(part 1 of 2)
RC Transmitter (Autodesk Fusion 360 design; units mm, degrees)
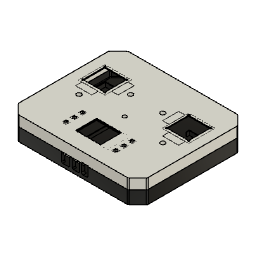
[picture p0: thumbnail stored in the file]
sketch "Skizze3" plane through (0, 0, 0) normal (0, 0, 1) x axis (1, 0, 0)
  line L1 (-100, 70) -> (-100, 0)
  line L2 (-85, 85) -> (-100, 70)
  line L3 (85, 85) -> (-85, 85)
  line L4 (100, 70) -> (85, 85)
  line L5 (100, -70) -> (100, 70)
  line L6 (85, -85) -> (100, -70)
  line L7 (-85, -85) -> (85, -85)
  line L8 (-100, -70) -> (-85, -85)
  line L9 (-100, 0) -> (-100, -70)
  line L10 (-95, 67.5) -> (-95, 0)
  line L11 (-82.5, 80) -> (0, 80)
  line L12 (-82.5, 80) -> (-95, 67.5)
  line L13 (82.5, 80) -> (0, 80)
  line L14 (95, 67.5) -> (95, 0)
  line L15 (82.5, 80) -> (95, 67.5)
  line L16 (95, -67.5) -> (95, 0)
  line L17 (-95, -67.5) -> (-95, 0)
  line L18 (-82.5, -80) -> (0, -80)
  line L19 (82.5, -80) -> (0, -80)
  line L20 (95, -67.5) -> (82.5, -80)
  line L21 (-95, -67.5) -> (-82.5, -80)
  point P11 (-95, 0)
  point P12 (-95, 67.5)
  point P13 (0, 80)
  point P14 (-82.5, 80)
  point P15 (82.5, 80)
  point P16 (95, 0)
  point P17 (95, 67.5)
  point P18 (95, -67.5)
  point P19 (-95, -67.5)
  point P20 (0, -80)
  point P21 (-82.5, -80)
  point P22 (82.5, -80)
  vertical L1
  perpendicular L1 L3
  perpendicular L3 L5
  perpendicular L4 L6
  perpendicular L5 L7
  perpendicular L6 L8
  perpendicular L7 L9
  parallel L1 L10
  horizontal L11
  perpendicular L10 L13
  perpendicular L11 L14
  parallel L14 L16
  parallel L10 L17
  perpendicular L10 L18
  parallel L18 L19
  parallel L6 L20
  dimension "d3" distance P11 P12 = 67.5
  dimension "d4" distance P13 P14 = 82.5
  dimension "d5" distance P13 P15 = 82.5
  dimension "d6" distance P16 P17 = 67.5
  dimension "d7" distance P16 P18 = 67.5
  dimension "d8" distance P11 P19 = 67.5
  dimension "d9" distance P20 P21 = 82.5
  dimension "d10" distance P20 P22 = 82.5
extrude "Extrusion1" new body sketch "Skizze3" profile of L1 L2 L3 L4 L5 L6 L7 L8 L9 along normal blind 5
extrude "Extrusion2" cut of existing geometry blind -5
extrude "Extrusion3" add sketch "Skizze3" profile of L10 L11 L12 L13 L14 L15 L16 L17 L18 L19 L20 L21 along normal blind 5
extrude "Extrusion4" add sketch "Skizze3" along normal blind 25
sketch "Skizze5" plane through (0, 0, 25) normal (0, 0, 1) x axis (-1, 0, 0)
  line L1 (82.5, 80) -> (-82.5, 80)
  line L2 (95, 67.5) -> (82.5, 80)
  line L3 (95, -67.5) -> (95, 67.5)
  line L4 (82.5, -80) -> (95, -67.5)
  line L5 (-82.5, -80) -> (82.5, -80)
  line L6 (-95, -67.5) -> (-82.5, -80)
  line L7 (-95, 67.5) -> (-95, -67.5)
  line L8 (-82.5, 80) -> (-95, 67.5)
  line L9 (85, 85) -> (100, 70)
  line L10 (-85, 85) -> (85, 85)
  line L11 (-100, 70) -> (-85, 85)
  line L12 (-100, -70) -> (-100, 70)
  line L13 (-85, -85) -> (-100, -70)
  line L14 (85, -85) -> (-85, -85)
  line L15 (100, -70) -> (85, -85)
  line L16 (100, 70) -> (100, -70)
  line L17 (97.6238, -69.3738) -> (97.6238, 0.1262)
  line L18 (84.3762, -82.6262) -> (-0.1238, -82.6262)
  line L19 (84.3762, -82.6262) -> (97.6238, -69.3738)
  line L20 (-84.6238, -82.6262) -> (-0.1238, -82.6262)
  line L21 (-84.375, 82.625) -> (0.125, 82.625)
  line L22 (84.625, 82.625) -> (0.125, 82.625)
  line L23 (97.6238, 69.6262) -> (97.6238, 0.1262)
  line L24 (-97.625, 69.375) -> (-97.625, -0.125)
  line L25 (-97.625, -69.625) -> (-97.625, -0.125)
  line L26 (-84.6238, -82.6262) -> (-97.625, -69.625)
  line L27 (-84.375, 82.625) -> (-97.625, 69.375)
  line L28 (97.6238, 69.6262) -> (84.625, 82.625)
  line L29 (27.5, 80) -> (-27.5, 80)
  line L30 (27.5, 85) -> (27.5, 80)
  line L31 (-27.5, 85) -> (27.5, 85)
  line L32 (-27.5, 80) -> (-27.5, 85)
  line L33 (27.5, 85) -> (-27.5, 80)
  line L34 (-27.5, 85) -> (27.5, 80)
  point P34 (0, 82.5)
  point P18 (97.6238, 0.1262)
  point P19 (97.6238, -69.3738)
  point P20 (-0.1238, -82.6262)
  point P21 (84.3762, -82.6262)
  point P22 (-84.6238, -82.6262)
  point P23 (0.125, 82.625)
  point P24 (-84.375, 82.625)
  point P25 (84.625, 82.625)
  point P26 (97.6238, 69.6262)
  point P27 (-97.625, -0.125)
  point P28 (-97.625, 69.375)
  point P29 (-97.625, -69.625)
  point P32 (27.5, 85)
  point P33 (-27.5, 85)
  vertical L17
  parallel L5 L18
  parallel L5 L20
  parallel L1 L21
  parallel L21 L22
  vertical L23
  vertical L24
  parallel L24 L25
  parallel L26 L28
  perpendicular L29 L30
  parallel L29 L31
  parallel L30 L32
  horizontal L29
  coincident L33 P34
  coincident L34 P34
  dimension "d17" distance P18 P19 = 69.5
  dimension "d18" distance P20 P21 = 84.5
  dimension "d19" distance P20 P22 = 84.5
  dimension "d20" distance P23 P24 = 84.5
  dimension "d21" distance P23 P25 = 84.5
  dimension "d22" distance P18 P26 = 69.5
  dimension "d23" distance P27 P28 = 69.5
  dimension "d24" distance P27 P29 = 69.5
  dimension "d27" distance P32 P33 = 55
extrude "Extrusion5" add sketch "Skizze5" profile of L9 L10 L11 L12 L13 L14 L15 L16 L17 L18 L19 L20 L21 L22 L23 L24 L25 L26 L27 L28 along normal blind 5
extrude "Extrusion6" cut sketch "Skizze5" profile of L1 L21 L22 L29 L30 L32 against normal blind 20
extrude "Extrusion7" cut sketch "Skizze5" profile of L10 L21 L22 L30 L31 L32 against normal blind 20
extrude "Extrusion8" cut sketch "Skizze5" profile of L10 L21 L22 L30 L31 L32 along normal blind 5
sketch "Skizze8" plane through (0, 0, 5) normal (0, 0, 1) x axis (-1, 0, 0)
  line L1 (27.5, 80) -> (82.5, 80)
  line L2 (27.5, 85) -> (27.5, 80)
  line L3 (-27.5, 85) -> (27.5, 85)
  line L4 (-27.5, 80) -> (-27.5, 85)
  line L5 (-82.5, 80) -> (-27.5, 80)
  line L6 (-95, 67.5) -> (-82.5, 80)
  line L7 (-95, -67.5) -> (-95, 67.5)
  line L8 (-82.5, -80) -> (-95, -67.5)
  line L9 (82.5, -80) -> (-82.5, -80)
  line L10 (95, -67.5) -> (82.5, -80)
  line L11 (95, 67.5) -> (95, -67.5)
  line L12 (82.5, 80) -> (95, 67.5)
  line L13 (27.5, -22.5) -> (27.5, 80)
  line L14 (-26.5, -22.5) -> (27.5, -22.5)
  line L15 (-26.5001, 80) -> (-26.5, -22.5)
  line L16 (28.5, 80) -> (28.5, 79.5)
  line L17 (28.5, -22.5) -> (28.5, 79.5)
  line L18 (28.5, -23.5) -> (28.5, -22.5)
  line L19 (-27.5, -23.5) -> (28.5, -23.5)
  line L20 (-27.5001, 80) -> (-27.5, -23.5)
  line L21 (-27.5, 80) -> (-27.5001, 80)
  line L22 (-27.5, 80) -> (-27.5001, 80)
  line L23 (27.5, 80) -> (28.5, 80)
  line L24 (-44.5, -9.5) -> (-85.5, -9.5)
  line L25 (-44.5, -50.5) -> (-44.5, -9.5)
  line L26 (-85.5, -50.5) -> (-44.5, -50.5)
  line L27 (-85.5, -9.5) -> (-85.5, -50.5)
  line L28 (-44.5, -50.5) -> (-85.5, -9.5)
  line L29 (-85.5, -50.5) -> (-44.5, -9.5)
  line L30 (-43.5, -51.5) -> (-43.5, -51)
  line L31 (-43.5, -51) -> (-43.5, -51.5)
  line L32 (-86, -8.5) -> (-43.5, -8.5)
  line L33 (-86.5, -8.5) -> (-86, -8.5)
  line L34 (-86.5, -51.5) -> (-86.5, -8.5)
  line L35 (-43.5, -51.5) -> (-86.5, -51.5)
  line L36 (-43.5, -51) -> (-43.5, -42.5)
  line L37 (-43.5, -8.5) -> (-43.5, -42.5)
  line L38 (0, -44) -> (0, -36)
  line L39 (44.5, -50.5) -> (85.5, -9.5)
  line L40 (44.5, -50.5) -> (44.5, -9.5)
  line L41 (85.5, -9.5) -> (85.5, -50.5)
  line L42 (43.5, -51.5) -> (43.5, -51)
  line L43 (43.5, -51.5) -> (86.5, -51.5)
  line L44 (86.5, -51.5) -> (86.5, -8.5)
  line L45 (43.5, -51) -> (43.5, -51.5)
  line L46 (43.5, -51) -> (43.5, -42.5)
  line L47 (85.5, -50.5) -> (44.5, -50.5)
  line L48 (85.5, -50.5) -> (44.5, -9.5)
  line L49 (44.5, -9.5) -> (85.5, -9.5)
  line L50 (86.5, -8.5) -> (86, -8.5)
  line L51 (43.5, -8.5) -> (43.5, -42.5)
  line L52 (86, -8.5) -> (43.5, -8.5)
  line L53 (-43.5, -46.5) -> (-44.5, -46.5)
  line L54 (-43.5, -12.5) -> (-43.5, -46.5)
  line L55 (-44.5, -12.5) -> (-43.5, -12.5)
  line L56 (-44.5, -46.5) -> (-44.5, -12.5)
  line L57 (-43.5, -12.5) -> (-44.5, -46.5)
  line L58 (-44.5, -12.5) -> (-43.5, -46.5)
  line L59 (-47.5, -9.5) -> (-81.5, -9.5)
  line L60 (-47.5, -8.5) -> (-47.5, -9.5)
  line L61 (-81.5, -8.5) -> (-47.5, -8.5)
  line L62 (-81.5, -9.5) -> (-81.5, -8.5)
  line L63 (-47.5, -8.5) -> (-81.5, -9.5)
  line L64 (-81.5, -8.5) -> (-47.5, -9.5)
  line L65 (44.5, -12.5) -> (43.5, -46.5)
  line L66 (43.5, -12.5) -> (44.5, -46.5)
  line L67 (44.5, -12.5) -> (43.5, -12.5)
  line L68 (44.5, -46.5) -> (44.5, -12.5)
  line L69 (43.5, -12.5) -> (43.5, -46.5)
  line L70 (43.5, -46.5) -> (44.5, -46.5)
  line L71 (47.5, -9.5) -> (81.5, -9.5)
  line L72 (47.5, -8.5) -> (47.5, -9.5)
  line L73 (47.5, -8.5) -> (81.5, -9.5)
  line L74 (81.5, -8.5) -> (47.5, -9.5)
  line L75 (81.5, -8.5) -> (47.5, -8.5)
  line L76 (81.5, -9.5) -> (81.5, -8.5)
  line L77 (-90, 34) -> (-40, 34)
  line L78 (-90, 62) -> (-90, 34)
  line L79 (-40, 62) -> (-90, 62)
  line L80 (-40, 34) -> (-40, 62)
  line L81 (-39, 63) -> (-91, 63)
  line L82 (-39, 33) -> (-39, 63)
  line L83 (-91, 33) -> (-39, 33)
  line L84 (-91, 63) -> (-91, 33)
  line L85 (91, 63) -> (91, 33)
  line L86 (40, 34) -> (40, 62)
  line L87 (90, 34) -> (40, 34)
  line L88 (91, 33) -> (39, 33)
  line L89 (39, 63) -> (91, 63)
  line L90 (40, 62) -> (90, 62)
  line L91 (90, 62) -> (90, 34)
  line L92 (39, 33) -> (39, 63)
  line L93 (16.5, 80) -> (27.5, 80)
  line L94 (16.5, 85) -> (16.5, 80)
  line L95 (27.5, 85) -> (16.5, 85)
  line L96 (27.5, 80) -> (27.5, 85)
  line L97 (-23.0001, 80) -> (-27.5, 80)
  line L98 (-23.0001, 85) -> (-23.0001, 80)
  line L99 (-27.5, 85) -> (-23.0001, 85)
  line L100 (-27.5, 80) -> (-27.5, 85)
  line L101 (-8.5001, 85) -> (-12.0001, 85)
  line L102 (-8.5001, 80) -> (-8.5001, 85)
  line L103 (-12.0001, 80) -> (-8.5001, 80)
  line L104 (-12.0001, 85) -> (-12.0001, 80)
  line L105 (0.7499, 85) -> (6.7499, 85)
  line L106 (0.7499, 80) -> (0.7499, 85)
  line L107 (6.7499, 80) -> (0.7499, 80)
  line L108 (6.7499, 85) -> (6.7499, 80)
  line L109 (-40, 36) -> (-39, 36)
  line L110 (-40, 60) -> (-40, 36)
  line L111 (-39, 60) -> (-40, 60)
  line L112 (-39, 36) -> (-39, 60)
  line L113 (39, 36) -> (40, 36)
  line L114 (39, 60) -> (39, 36)
  line L115 (40, 60) -> (39, 60)
  line L116 (40, 36) -> (40, 60)
  circle C1 centre (-23.7501, 65.5) radius 1
  circle C2 centre (25, 64.25) radius 1
  circle C3 centre (-23.75, -17.25) radius 1
  circle C4 centre (24.75, -10.75) radius 1
  point P3 (27.5, 80)
  point P14 (27.5, 80)
  point P19 (28.5, 80)
  point P6 (-27.5, 80)
  point P24 (-27.5, 80)
  point P25 (27.5, 80)
  point P30 (-65, -30)
  point P26 (-85.5, -9.5)
  point P44 (85.5, -9.5)
  point P27 (-44.5, -9.5)
  point P49 (44.5, -9.5)
  point P28 (-44.5, -50.5)
  point P46 (44.5, -50.5)
  point P29 (-85.5, -50.5)
  point P50 (85.5, -50.5)
  point P51 (65, -30)
  point P31 (-43.5, -51)
  point P45 (43.5, -51)
  point P32 (-43.5, -51.5)
  point P48 (43.5, -51.5)
  point P33 (-43.5, -8.5)
  point P42 (43.5, -8.5)
  point P34 (-86, -8.5)
  point P40 (86, -8.5)
  point P35 (-86.5, -8.5)
  point P41 (86.5, -8.5)
  point P36 (-86.5, -51.5)
  point P47 (86.5, -51.5)
  point P37 (-43.5, -42.5)
  point P43 (43.5, -42.5)
  point P56 (-44, -29.5)
  point P61 (-64.5, -9)
  point P65 (43.5, -42.5)
  point P52 (-44.5, -46.5)
  point P67 (44.5, -46.5)
  point P53 (-43.5, -46.5)
  point P64 (43.5, -46.5)
  point P54 (-43.5, -12.5)
  point P62 (43.5, -12.5)
  point P55 (-44.5, -12.5)
  point P66 (44.5, -12.5)
  point P63 (44, -29.5)
  point P57 (-81.5, -9.5)
  point P72 (81.5, -9.5)
  point P58 (-47.5, -9.5)
  point P70 (47.5, -9.5)
  point P59 (-47.5, -8.5)
  point P71 (47.5, -8.5)
  point P60 (-81.5, -8.5)
  point P68 (81.5, -8.5)
  point P69 (64.5, -9)
  point P73 (-40, 34)
  point P87 (40, 34)
  point P74 (-90, 34)
  point P82 (90, 34)
  point P75 (-90, 62)
  point P84 (90, 62)
  point P76 (-40, 62)
  point P81 (40, 62)
  point P77 (-91, 63)
  point P86 (91, 63)
  point P78 (-39, 63)
  point P85 (39, 63)
  point P79 (-39, 33)
  point P83 (39, 33)
  point P80 (-91, 33)
  point P88 (91, 33)
  point P90 (16.5, 85)
  point P92 (-27.5, 80)
  point P17 (-26.5001, 80)
  point P96 (-12.0001, 85)
  point P100 (6.7499, 85)
  point P108 (-39, 36)
  point P112 (40, 36)
  point P15 (27.5, -22.5)
  point P16 (-26.5, -22.5)
  point P1 (0, 0)
  point P4 (27.5, 85)
  point P21 (28.5, -23.5)
  point P22 (-27.5, -23.5)
  point P93 (-23.0001, 80)
  point P98 (-8.5001, 80)
  point P99 (-12.0001, 80)
  point P102 (0.7499, 80)
  point P103 (6.7499, 80)
  point P104 (-23.7501, 65.5)
  point P105 (25, 64.25)
  point P106 (-23.75, -17.25)
  point P107 (24.75, -10.75)
  point P109 (-40, 36)
  point P111 (-39, 60)
  point P115 (40, 60)
  point P113 (39, 36)
  coincident P3 P14
  perpendicular L1 L13
  perpendicular L13 L14
  coincident L1 P19
  perpendicular L1 L16
  perpendicular L1 L17
  parallel L17 L18
  perpendicular L18 L19
  coincident P6 P24
  coincident P3 P25
  perpendicular L24 L25
  parallel L24 L26
  parallel L25 L27
  horizontal L24
  coincident L28 P30
  coincident L29 P30
  perpendicular L26 L30
  perpendicular L25 L32
  perpendicular L25 L33
  perpendicular L33 L34
  parallel L31 L36
  perpendicular L32 L37
  vertical L38
  symmetric P26 L38 P44
  symmetric P27 L38 P49
  symmetric P28 L38 P46
  symmetric P29 L38 P50
  symmetric P30 L38 P51
  symmetric P31 L38 P45
  symmetric P32 L38 P48
  symmetric P33 L38 P42
  symmetric P34 L38 P40
  symmetric P35 L38 P41
  symmetric P36 L38 P47
  symmetric P37 L38 P43
  perpendicular L53 L54
  parallel L53 L55
  parallel L54 L56
  horizontal L53
  coincident L57 P56
  coincident L58 P56
  perpendicular L59 L60
  parallel L59 L61
  parallel L60 L62
  horizontal L59
  coincident L63 P61
  coincident L64 P61
  symmetric P37 L38 P65
  symmetric L38 P52 P67
  symmetric L38 P53 P64
  symmetric L38 P54 P62
  symmetric L38 P55 P66
  symmetric L38 P56 P63
  symmetric L38 P57 P72
  symmetric L38 P58 P70
  symmetric L38 P59 P71
  symmetric L38 P60 P68
  symmetric L38 P61 P69
  horizontal L77
  vertical L78
  horizontal L79
  vertical L80
  symmetric L38 P73 P87
  symmetric L38 P74 P82
  symmetric L38 P75 P84
  symmetric L38 P76 P81
  symmetric L38 P77 P86
  symmetric L38 P78 P85
  symmetric L38 P79 P83
  symmetric L38 P80 P88
  horizontal L93
  vertical L94
  horizontal L95
  vertical L96
  coincident L3 P90
  horizontal L97
  vertical L98
  horizontal L99
  vertical L100
  coincident P6 P92
  coincident P17 L97
  horizontal L101
  vertical L102
  horizontal L103
  vertical L104
  coincident L3 P96
  horizontal L105
  vertical L106
  horizontal L107
  vertical L108
  coincident L3 P100
  horizontal L109
  vertical L110
  horizontal L111
  vertical L112
  coincident L82 P108
  horizontal L113
  vertical L114
  horizontal L115
  vertical L116
  coincident L86 P112
  dimension "d34" distance P14 P15 = 102.5
  dimension "d35" distance P15 P16 = 54
  dimension "d38" distance P28 P29 = 41
  dimension "d39" distance P27 P28 = 41
  dimension "d40" distance L5 P30 = 110
  dimension "d41" distance P1 P30 = 65
  dimension "d59" distance P73 P74 = 50
  dimension "d60" distance P73 P76 = 28
  dimension "d61" distance L7 P74 = 5
  dimension "d62" distance L5 P76 = 18
  dimension "d63" = -1
  dimension "d86" distance P4 P90 = 11
  dimension "d88" distance L15 L20 = 1
  dimension "d89" distance L13 L17 = 1
  dimension "d91" distance P21 P22 = 56
  dimension "d94" distance L14 L19 = 1
  dimension "d95" distance L9 L19 = 56.5
  dimension "d96" distance P17 P93 = 3.5
  dimension "d99" distance L98 L104 = 11
  dimension "d100" distance P98 P99 = 3.5
  dimension "d102" distance L102 L106 = 9.25
  dimension "d103" distance P102 P103 = 6
  dimension "d116" diameter C1 = 2
  dimension "d117" distance L15 P104 = 2.75
  dimension "d118" distance L97 P104 = 14.5
  dimension "d119" diameter C2 = 2
  dimension "d120" distance L93 P105 = 15.75
  dimension "d121" distance L13 P105 = 2.5
  dimension "d124" diameter C3 = 2
  dimension "d125" diameter C4 = 2
  dimension "d126" distance P104 P106 = 82.75
  dimension "d127" distance L15 P106 = 2.75
  dimension "d128" distance P105 P107 = 75
  dimension "d129" distance L13 P107 = 2.75
  dimension "d140" distance P108 P109 = 1
  dimension "d141" distance P108 P111 = 24
  dimension "d142" distance P79 P108 = 3
  dimension "d143" distance P112 P115 = 24
  dimension "d144" distance P112 P113 = 1
  dimension "d145" distance P83 P112 = 3
extrude "Extrusion9" add sketch "Skizze8" profile of L1 L5 L13 L14 L15 L16 L17 L18 L19 L20 L21 L22 L23 along normal blind 3.5
extrude "Extrusion10" add sketch "Skizze8" profile of L24 L25 L26 L27 L30 L31 L32 L33 L34 L35 L36 L37 along normal blind 3.3
extrude "Extrusion11" add sketch "Skizze8" profile of L40 L41 L42 L43 L44 L45 L46 L47 L49 L50 L51 L52 along normal blind 3.3
extrude "Extrusion12" cut sketch "Skizze8" profile of L25 L36 L37 L53 L54 L55 L56 along normal blind 3.3
extrude "Extrusion13" cut sketch "Skizze8" profile of L24 L32 L59 L60 L61 L62 along normal blind 3.3
extrude "Extrusion14" cut sketch "Skizze8" profile of L40 L46 L51 L67 L68 L69 L70 along normal blind 3.3
extrude "Extrusion15" cut sketch "Skizze8" profile of L49 L52 L71 L72 L75 L76 along normal blind 3.3
extrude "Extrusion16" add sketch "Skizze8" profile of L85 L86 L87 L88 L89 L90 L91 L92 along normal blind 3.3
extrude "Extrusion17" add sketch "Skizze8" profile of L77 L78 L79 L80 L81 L82 L83 L84 along normal blind 3.3
sketch "Skizze10" plane through (0, 80, 0) normal (0, -1, 0) x axis (1, 0, 0)
  line L1 (82.5, 5) -> (-82.5, 5)
  line L2 (82.5, 25) -> (82.5, 5)
  line L3 (-82.5, 25) -> (82.5, 25)
  line L4 (-82.5, 5) -> (-82.5, 25)
  line L5 (-6.2939, 32.4535) -> (-6.2939, 21.624)
  line L6 (6.7061, 32.4535) -> (-6.2939, 32.4535)
  line L7 (6.4991, 19.8929) -> (6.7061, 32.4535)
  line L8 (6.5, 20) -> (-6.5, 20)
  line L9 (6.5, 13.5) -> (6.5, 20)
  line L10 (-6.5, 13.5) -> (6.5, 13.5)
  line L11 (-6.5, 20) -> (-6.5, 13.5)
  circle C1 centre (0, 20) radius 6.5
  point P7 (-6.2939, 21.624)
  point P10 (6.4991, 19.8929)
  point P11 (-6.5, 20)
  point P8 (-6.2939, 32.4535)
  point P9 (6.7061, 32.4535)
  coincident C1 P7
  perpendicular L3 L5
  perpendicular L5 L6
  coincident C1 P10
  tangent C1 L7
  horizontal L8
  vertical L9
  horizontal L10
  vertical L11
  coincident C1 P11
  dimension "d68" diameter C1 = 13
  dimension "d69" distance P8 P9 = 13
extrude "Extrusion18" cut sketch "Skizze10" profile of C1 against normal blind 5
extrude "Extrusion19" cut sketch "Skizze10" profile of L3 C1 L5 L6 L7 against normal blind 5
fillet "Abrundung1" radius 3
fillet "Abrundung2" radius 3
fillet "Abrundung3" radius 3
fillet "Abrundung4" radius 3
fillet "Abrundung5" radius 3
fillet "Abrundung6" radius 3
fillet "Abrundung7" radius 3
fillet "Abrundung8" radius 3
extrude "Extrusion20" add sketch "Skizze8" profile of L2 L3 L4 L93 L94 L95 L96 L97 L98 L99 L100 along normal blind 5
extrude "Extrusion21" add of existing geometry blind 1.5
extrude "Extrusion22" add sketch "Skizze8" profile of L3 L101 L102 L103 L104 L105 L106 L107 L108 along normal blind 5
extrude "Extrusion23" add of existing geometry blind 15
extrude "Extrusion24" add of existing geometry blind 11
extrude "Extrusion25" add of existing geometry blind 4.5
extrude "Extrusion77" add of existing geometry blind 5
extrude "Extrusion26" add sketch "Skizze8" profile of C1 C2 along normal blind 5
extrude "Extrusion27" add sketch "Skizze8" profile of C3 C4 along normal blind 5
fillet "Abrundung13" radius 3
fillet "Abrundung14" radius 3
fillet "Abrundung15" radius 3
fillet "Abrundung16" radius 3
fillet "Abrundung17" radius 3
fillet "Abrundung18" radius 3
fillet "Abrundung19" radius 3
fillet "Abrundung20" radius 3
extrude "Extrusion28" cut sketch "Skizze8" profile of L86 L92 L113 L114 L115 L116 along normal blind 3.3
extrude "Extrusion29" cut sketch "Skizze8" profile of L80 L82 L109 L110 L111 L112 along normal blind 3.3
fillet "Abrundung21" radius 1
fillet "Abrundung22" radius 1
fillet "Abrundung23" radius 1
fillet "Abrundung24" radius 1
fillet "Abrundung25" radius 1
sketch "Skizze11" plane through (0, 0, 30) normal (0, 0, 1) x axis (-1, 0, 0)
  line L1 (27.5, 85) -> (83.7574, 85)
  line L2 (16.5, 85) -> (27.5, 85)
  line L3 (83.7574, -85) -> (6.2939, -85)
  line L4 (99.1213, -70.8787) -> (85.8787, -84.1213)
  line L5 (100, 68.7574) -> (100, -68.7574)
  line L6 (85.8787, 84.1213) -> (99.1213, 70.8787)
  line L7 (-100, -70) -> (-85, -85)
  line L8 (-100, 70) -> (-100, -70)
  line L9 (-85, 85) -> (-100, 70)
  line L10 (85, 85) -> (-85, 85)
  line L11 (100, 70) -> (85, 85)
  line L12 (100, 0) -> (100, 70)
  line L13 (100, -70) -> (100, 0)
  line L14 (-85, -85) -> (85, -85)
  line L15 (85, -85) -> (100, -70)
  line L16 (82.5, -80) -> (0, -80)
  line L17 (-82.5, -80) -> (0, -80)
  line L18 (-82.5, -80) -> (-95, -67.5)
  line L19 (-95, -67.5) -> (-95, 0)
  line L20 (-95, 67.5) -> (-95, 0)
  line L21 (-95, 67.5) -> (-82.5, 80)
  line L22 (-82.5, 80) -> (0, 80)
  line L23 (82.5, 80) -> (0, 80)
  line L24 (95, 67.5) -> (82.5, 80)
  line L25 (95, 67.5) -> (95, 0)
  line L26 (82.5, -80) -> (95, -67.5)
  line L27 (95, -67.5) -> (95, 0)
  line L28 (85, -85) -> (100, -70)
  line L29 (-100, -70) -> (-85, -85)
  line L30 (-85, 85) -> (-100, 70)
  line L31 (-100, -70) -> (-100, 70)
  line L32 (85, 85) -> (-85, 85)
  line L33 (100, 70) -> (85, 85)
  line L34 (100, -70) -> (100, 70)
  line L35 (-95, -67.5) -> (-82.5, -80)
  line L36 (-95, 67.5) -> (-95, -67.5)
  line L37 (-82.5, 80) -> (-95, 67.5)
  line L38 (82.5, 80) -> (-82.5, 80)
  line L39 (95, 67.5) -> (82.5, 80)
  line L40 (95, -67.5) -> (95, 67.5)
  line L41 (82.5, -80) -> (95, -67.5)
  line L42 (-82.5, -80) -> (82.5, -80)
  line L43 (84.3762, -82.6262) -> (-0.1238, -82.6262)
  line L44 (-84.6238, -82.6262) -> (-0.1238, -82.6262)
  line L45 (-84.6238, -82.6262) -> (-97.625, -69.625)
  line L46 (-97.625, -69.625) -> (-97.625, -0.125)
  line L47 (-97.625, 69.375) -> (-97.625, -0.125)
  line L48 (-84.375, 82.625) -> (-97.625, 69.375)
  line L49 (-84.375, 82.625) -> (0.125, 82.625)
  line L50 (84.625, 82.625) -> (0.125, 82.625)
  line L51 (97.6238, 69.6262) -> (84.625, 82.625)
  line L52 (97.6238, 69.6262) -> (97.6238, 0.1262)
  line L53 (84.3762, -82.6262) -> (97.6238, -69.3738)
  line L54 (97.6238, -69.3738) -> (97.6238, 0.1262)
  line L55 (84.3762, -82.6262) -> (97.6238, -69.3738)
  line L56 (-84.6238, -82.6262) -> (84.3762, -82.6262)
  line L57 (-97.625, -69.625) -> (-84.6238, -82.6262)
  line L58 (-97.625, 69.375) -> (-97.625, -69.625)
  line L59 (-84.375, 82.625) -> (-97.625, 69.375)
  line L60 (84.625, 82.625) -> (-84.375, 82.625)
  line L61 (97.6238, 69.6262) -> (84.625, 82.625)
  line L62 (97.6238, 69.6262) -> (97.6238, -69.3738)
  line L63 (-8.333, 80) -> (0.667, 80)
  line L64 (-8.333, 85) -> (-8.333, 80)
  line L65 (0.667, 85) -> (-8.333, 85)
  line L66 (0.667, 80) -> (0.667, 85)
  line L67 (7.4022, 80) -> (16.4022, 80)
  line L68 (7.4022, 85) -> (7.4022, 80)
  line L69 (16.4022, 85) -> (7.4022, 85)
  line L70 (16.4022, 80) -> (16.4022, 85)
  arc A1 centre (83.7574, 82) radius 3 clockwise from (83.7574, 85) to (85.8787, 84.1213)
  arc A2 centre (83.7574, -82) radius 3 clockwise from (85.8787, -84.1213) to (83.7574, -85)
  arc A3 centre (97, -68.7574) radius 3 clockwise from (100, -68.7574) to (99.1213, -70.8787)
  arc A4 centre (97, 68.7574) radius 3 clockwise from (99.1213, 70.8787) to (100, 68.7574)
  point P31 (100, -70)
  point P60 (100, -70)
  point P32 (85, -85)
  point P61 (85, -85)
  point P33 (-85, -85)
  point P62 (-85, -85)
  point P19 (-100, -70)
  point P63 (-100, -70)
  point P21 (-100, 70)
  point P64 (-100, 70)
  point P24 (-85, 85)
  point P65 (-85, 85)
  point P66 (-100, 70)
  point P67 (-85, 85)
  point P26 (85, 85)
  point P68 (85, 85)
  point P69 (85, 85)
  point P28 (100, 70)
  point P70 (100, 70)
  point P71 (100, -70)
  point P39 (-82.5, -80)
  point P72 (-82.5, -80)
  point P43 (-95, -67.5)
  point P73 (-95, -67.5)
  point P74 (-95, -67.5)
  point P45 (-95, 67.5)
  point P75 (-95, 67.5)
  point P76 (-95, 67.5)
  point P46 (-82.5, 80)
  point P77 (-82.5, 80)
  point P78 (-82.5, 80)
  point P51 (82.5, 80)
  point P79 (82.5, 80)
  point P53 (95, 67.5)
  point P80 (95, 67.5)
  point P55 (95, 67.5)
  point P81 (95, 67.5)
  point P59 (95, -67.5)
  point P82 (95, -67.5)
  point P83 (95, -67.5)
  point P57 (82.5, -80)
  point P84 (82.5, -80)
  point P37 (82.5, -80)
  point P85 (82.5, -80)
  point P106 (97.6238, -69.3738)
  point P110 (97.6238, -69.3738)
  point P87 (84.3762, -82.6262)
  point P111 (84.3762, -82.6262)
  point P112 (84.3762, -82.6262)
  point P89 (-84.6238, -82.6262)
  point P113 (-84.6238, -82.6262)
  point P90 (-97.625, -69.625)
  point P114 (-97.625, -69.625)
  point P115 (-97.625, -69.625)
  point P96 (-97.625, 69.375)
  point P116 (-97.625, 69.375)
  point P95 (-97.625, 69.375)
  point P117 (-97.625, 69.375)
  point P97 (-84.375, 82.625)
  point P118 (-84.375, 82.625)
  point P119 (-84.375, 82.625)
  point P101 (84.625, 82.625)
  point P120 (84.625, 82.625)
  point P105 (97.6238, 69.6262)
  point P121 (97.6238, 69.6262)
  point P122 (97.6238, -69.3738)
  point P123 (0.667, 80)
  point P127 (16.4022, 80)
  point P124 (-8.333, 80)
  point P128 (7.4022, 80)
  coincident P31 P60
  coincident P32 P61
  coincident P33 P62
  coincident P19 P63
  coincident P21 P64
  coincident P24 P65
  coincident P21 P66
  coincident P24 P67
  coincident P26 P68
  coincident P26 P69
  coincident P28 P70
  coincident P31 P71
  coincident P39 P72
  coincident P43 P73
  coincident P43 P74
  coincident P45 P75
  coincident P45 P76
  coincident P46 P77
  coincident P46 P78
  coincident P51 P79
  coincident P53 P80
  coincident P55 P81
  coincident P59 P82
  coincident P59 P83
  coincident P57 P84
  coincident P37 P85
  coincident P106 P110
  coincident P87 P111
  coincident P87 P112
  coincident P89 P113
  coincident P90 P114
  coincident P90 P115
  coincident P96 P116
  coincident P95 P117
  coincident P97 P118
  coincident P97 P119
  coincident P101 P120
  coincident P105 P121
  coincident P106 P122
  horizontal L63
  vertical L64
  horizontal L65
  vertical L66
  coincident L23 P123
  horizontal L67
  vertical L68
  horizontal L69
  vertical L70
  coincident L23 P127
  dimension "d343" distance P123 P124 = 9
  dimension "d344" distance P127 P128 = 9
extrude "Extrusion30" new body sketch "Skizze11" profile of A1 L1 L2 L3 A2 L4 A3 L5 A4 L6 L7 L8 L9 L10 L11 L12 L13 L14 L15 L16 L17 L18 L19 L20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 along normal blind 25
fillet "Abrundung26" radius 3
extrude "Extrusion31" add sketch "Skizze11" profile of L16 L17 L18 L19 L20 L21 L22 L23 L24 L25 L26 L27 L35 L36 L37 L38 L39 L40 L41 L42 L43 L44 L45 L46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 against normal blind 5
move "Verschieben1"
move "Verschieben2"
extrude "Extrusion32" cut of existing geometry blind -10
extrude "Extrusion33" cut of existing geometry blind -10
extrude "Extrusion34" cut of existing geometry blind -10
extrude "Extrusion35" cut of existing geometry blind -10
extrude "Extrusion36" cut of existing geometry blind -10
extrude "Extrusion37" cut of existing geometry blind -10
extrude "Extrusion38" cut of existing geometry blind -3
extrude "Extrusion39" cut of existing geometry blind -3
move "Verschieben3"
extrude "Extrusion40" add of existing geometry blind 7.5
extrude "Extrusion41" add of existing geometry blind 2.5
extrude "Extrusion42" add of existing geometry blind 1
sketch "Skizze12" plane through (0, 0, 36) normal (0, 0, 1) x axis (-1, 0, 0)
  line L1 (83.7574, -85) -> (-83.7574, -85)
  line L2 (99.1213, -70.8787) -> (85.8787, -84.1213)
  line L3 (100, 68.7574) -> (100, -68.7574)
  line L4 (85.8787, 84.1213) -> (99.1213, 70.8787)
  line L5 (-83.7574, 85) -> (83.7574, 85)
  line L6 (-99.1213, 70.8787) -> (-85.8787, 84.1213)
  line L7 (-100, -68.7574) -> (-100, 68.7574)
  line L8 (-85.8787, -84.1213) -> (-99.1213, -70.8787)
  line L9 (82.5, -80) -> (95, -67.5)
  line L10 (-82.5, -80) -> (82.5, -80)
  line L11 (-95, -67.5) -> (-82.5, -80)
  line L12 (-95, 67.5) -> (-95, -67.5)
  line L13 (-82.5, 80) -> (-95, 67.5)
  line L14 (82.5, 80) -> (-82.5, 80)
  line L15 (95, 67.5) -> (82.5, 80)
  line L16 (95, -67.5) -> (95, 67.5)
  arc A1 centre (-83.7574, -82) radius 3 clockwise from (-83.7574, -85) to (-85.8787, -84.1213)
  arc A2 centre (83.7574, -82) radius 3 clockwise from (85.8787, -84.1213) to (83.7574, -85)
  arc A3 centre (97, -68.7574) radius 3 clockwise from (100, -68.7574) to (99.1213, -70.8787)
  arc A4 centre (97, 68.7574) radius 3 clockwise from (99.1213, 70.8787) to (100, 68.7574)
  arc A5 centre (83.7574, 82) radius 3 clockwise from (83.7574, 85) to (85.8787, 84.1213)
  arc A6 centre (-83.7574, 82) radius 3 clockwise from (-85.8787, 84.1213) to (-83.7574, 85)
  arc A7 centre (-97, 68.7574) radius 3 clockwise from (-100, 68.7574) to (-99.1213, 70.8787)
  arc A8 centre (-97, -68.7574) radius 3 clockwise from (-99.1213, -70.8787) to (-100, -68.7574)
extrude "Extrusion43" add sketch "Skizze12" profile of L9 L10 L11 L12 L13 L14 L15 L16 against normal blind 5
sketch "Skizze13" plane through (0, 85, 0) normal (0, 1, 0) x axis (-1, 0, 0)
  line L1 (-83.7574, 20) -> (-83.7574, 36)
  line L2 (83.7574, 20) -> (-83.7574, 20)
  line L3 (83.7574, 36) -> (83.7574, 20)
  line L4 (-83.7574, 36) -> (83.7574, 36)
  line L5 (6.5, 20) -> (-6.5, 20)
  line L6 (6.5, 20.0001) -> (6.5, 20)
  line L7 (-6.5, 20.0001) -> (6.5, 20.0001)
  line L8 (-6.5, 20) -> (-6.5, 20.0001)
  line L9 (6.5, 20) -> (-6.5, 20)
  line L10 (6.5, 13.5) -> (6.5, 20)
  line L11 (-6.5, 13.5) -> (6.5, 13.5)
  line L12 (-6.5, 20) -> (-6.5, 13.5)
  circle C1 centre (0, 20) radius 6.5
  point P6 (0, 20)
  midpoint L2 P6
  horizontal L5
  horizontal L7
  vertical L8
  horizontal L9
  vertical L10
  horizontal L11
  vertical L12
  dimension "d185" diameter C1 = 13
extrude "Extrusion44" cut sketch "Skizze13" profile of L2 C1 against normal blind 27
extrude "Extrusion45" cut of existing geometry blind -0.7
extrude "Extrusion46" cut sketch "Skizze10" profile of L3 C1 against normal blind 4.5
extrude "Extrusion47" cut sketch "Skizze13" profile of C1 L10 L11 L12 against normal blind 9
sketch "Skizze14" plane through (0, 80, 0) normal (0, -1, 0) x axis (1, 0, 0)
  line L1 (6.5, 15) -> (6.5, 20)
  line L2 (82.5, 15) -> (6.5, 15)
  line L3 (82.5, 31) -> (82.5, 15)
  line L4 (-82.5, 31) -> (82.5, 31)
  line L5 (-82.5, 15) -> (-82.5, 31)
  line L6 (-6.5, 15) -> (-82.5, 15)
  line L7 (-6.5, 20) -> (-6.5, 15)
  line L8 (-6.5, 20) -> (6.5, 20)
  line L9 (-6.5, 26.5) -> (-6.5, 20)
  line L10 (6.5, 26.5) -> (-6.5, 26.5)
  line L11 (6.5, 20) -> (6.5, 26.5)
  arc A1 centre (0, 20) radius 6.5 clockwise from (-6.5, 20) to (6.5, 20)
  point P2 (6.5, 20)
  point P11 (6.5, 20)
  point P12 (-6.5, 20)
  horizontal L8
  vertical L9
  horizontal L10
  vertical L11
  coincident P2 P11
  dimension "d194" distance P11 P12 = 13
extrude "Extrusion48" cut sketch "Skizze14" profile of A1 L9 L10 L11 against normal blind 2.5
extrude "Extrusion49" cut sketch "Skizze10" profile of C1 L7 L9 L10 L11 against normal blind 2.5
extrude "Extrusion50" cut sketch "Skizze10" profile of C1 L7 L9 L10 L11 against normal blind 2.65
sketch "Skizze16" plane through (0, 0, 31) normal (0, 0, -1) x axis (1, 0, 0)
  line L1 (-95, 67.5) -> (-82.5, 80)
  line L2 (-95, -67.5) -> (-95, 67.5)
  line L3 (-82.5, -80) -> (-95, -67.5)
  line L4 (82.5, -80) -> (-82.5, -80)
  line L5 (95, -67.5) -> (82.5, -80)
  line L6 (95, 67.5) -> (95, -67.5)
  line L7 (82.5, 80) -> (95, 67.5)
  line L8 (-82.5, 80) -> (82.5, 80)
  line L9 (44.45, -8.6) -> (85.35, -8.6)
  line L10 (44.45, -49.5) -> (44.45, -8.6)
  line L11 (85.35, -49.5) -> (44.45, -49.5)
  line L12 (85.35, -8.6) -> (85.35, -49.5)
  line L13 (44.45, -49.5) -> (85.35, -8.6)
  line L14 (85.35, -49.5) -> (44.45, -8.6)
  line L15 (47.9, -46.05) -> (81.9, -46.05)
  line L16 (47.9, -12.05) -> (47.9, -46.05)
  line L17 (81.9, -12.05) -> (47.9, -12.05)
  line L18 (81.9, -46.05) -> (81.9, -12.05)
  line L19 (47.9, -12.05) -> (81.9, -46.05)
  line L20 (81.9, -12.05) -> (47.9, -46.05)
  line L21 (-85.35, -8.6) -> (-44.45, -8.6)
  line L22 (-85.35, -49.5) -> (-85.35, -8.6)
  line L23 (-44.45, -49.5) -> (-85.35, -49.5)
  line L24 (-44.45, -8.6) -> (-44.45, -49.5)
  line L25 (-85.35, -49.5) -> (-44.45, -8.6)
  line L26 (-44.45, -49.5) -> (-85.35, -8.6)
  line L27 (-81.9, -12.05) -> (-47.9, -12.05)
  line L28 (-81.9, -46.05) -> (-81.9, -12.05)
  line L29 (-47.9, -46.05) -> (-81.9, -46.05)
  line L30 (-47.9, -12.05) -> (-47.9, -46.05)
  line L31 (-81.9, -46.05) -> (-47.9, -12.05)
  line L32 (-47.9, -46.05) -> (-81.9, -12.05)
  line L33 (44.5, -9.5) -> (85.5, -9.5)
  line L34 (47.5, -9.5) -> (81.5, -9.5)
  line L35 (-4.35, 11.9349) -> (4.35, 11.9349)
  line L36 (-4.35, -1.5651) -> (-4.35, 11.9349)
  line L37 (4.35, -1.5651) -> (-4.35, -1.5651)
  line L38 (4.35, 11.9349) -> (4.35, -1.5651)
  line L39 (-4.35, -1.5651) -> (4.35, 11.9349)
  line L40 (4.35, -1.5651) -> (-4.35, 11.9349)
  line L41 (30, -22.55) -> (20, -22.55)
  line L42 (30, -23.55) -> (30, -22.55)
  line L43 (20, -23.55) -> (30, -23.55)
  line L44 (20, -22.55) -> (20, -23.55)
  line L45 (30, -23.55) -> (20, -22.55)
  line L46 (20, -23.55) -> (30, -22.55)
  line L47 (69.9779, 16.4499) -> (59.9779, 16.4499)
  line L48 (69.9779, 17.4499) -> (69.9779, 16.4499)
  line L49 (59.9779, 17.4499) -> (69.9779, 17.4499)
  line L50 (59.9779, 16.4499) -> (59.9779, 17.4499)
  line L51 (69.9779, 17.4499) -> (59.9779, 16.4499)
  line L52 (59.9779, 17.4499) -> (69.9779, 16.4499)
  line L53 (19.25, 29.4) -> (-19.25, 29.4)
  line L54 (19.25, 61.7) -> (19.25, 29.4)
  line L55 (-19.25, 61.7) -> (19.25, 61.7)
  line L56 (-19.25, 29.4) -> (-19.25, 61.7)
  line L57 (19.25, 61.7) -> (-19.25, 29.4)
  line L58 (-19.25, 61.7) -> (19.25, 29.4)
  line L59 (26.15, 27.9) -> (-20.25, 27.9)
  line L60 (26.15, 62.2) -> (26.15, 27.9)
  line L61 (-20.25, 62.2) -> (26.15, 62.2)
  line L62 (-20.25, 27.9) -> (-20.25, 62.2)
  line L63 (26.15, 62.2) -> (-20.25, 27.9)
  line L64 (-20.25, 62.2) -> (26.15, 27.9)
  line L65 (30.85, 27.3) -> (-25.55, 27.3)
  line L66 (30.85, 62.7) -> (30.85, 27.3)
  line L67 (-25.55, 62.7) -> (30.85, 62.7)
  line L68 (-25.55, 27.3) -> (-25.55, 62.7)
  line L69 (30.85, 62.7) -> (-25.55, 27.3)
  line L70 (-25.55, 62.7) -> (30.85, 27.3)
  line L71 (-35, 41.5) -> (-41.7, 41.5)
  line L72 (-35, 48.2) -> (-35, 41.5)
  line L73 (-41.7, 48.2) -> (-35, 48.2)
  line L74 (-41.7, 41.5) -> (-41.7, 48.2)
  line L75 (-35, 48.2) -> (-41.7, 41.5)
  line L76 (-41.7, 48.2) -> (-35, 41.5)
  line L77 (-35, 35.6) -> (-35, 28.9)
  line L78 (-41.7, 35.6) -> (-35, 28.9)
  line L79 (-35, 35.6) -> (-41.7, 28.9)
  line L80 (-41.7, 35.6) -> (-35, 35.6)
  line L81 (-35, 28.9) -> (-41.7, 28.9)
  line L82 (-41.7, 28.9) -> (-41.7, 35.6)
  line L83 (-41.7, 60.8) -> (-35, 54.1)
  line L84 (-35, 60.8) -> (-35, 54.1)
  line L85 (-35, 60.8) -> (-41.7, 54.1)
  line L86 (-41.7, 54.1) -> (-41.7, 60.8)
  line L87 (-35, 54.1) -> (-41.7, 54.1)
  line L88 (-41.7, 60.8) -> (-35, 60.8)
  line L89 (41.7, 47.9195) -> (35, 41.2195)
  line L90 (35, 35.3195) -> (41.7, 35.3195)
  line L91 (41.7, 60.5195) -> (35, 53.8195)
  line L92 (35, 41.2195) -> (35, 47.9195)
  line L93 (35, 47.9195) -> (41.7, 41.2195)
  line L94 (35, 28.6195) -> (35, 35.3195)
  line L95 (41.7, 47.9195) -> (41.7, 41.2195)
  line L96 (35, 35.3195) -> (41.7, 28.6195)
  line L97 (41.7, 60.5195) -> (41.7, 53.8195)
  line L98 (41.7, 28.6195) -> (35, 28.6195)
  line L99 (41.7, 35.3195) -> (41.7, 28.6195)
  line L100 (35, 53.8195) -> (35, 60.5195)
  line L101 (35, 60.5195) -> (41.7, 53.8195)
  line L102 (41.7, 35.3195) -> (35, 28.6195)
  line L103 (35, 47.9195) -> (41.7, 47.9195)
  line L104 (41.7, 53.8195) -> (35, 53.8195)
  line L105 (35, 60.5195) -> (41.7, 60.5195)
  line L106 (41.7, 41.2195) -> (35, 41.2195)
  line L107 (-29.9, -23.55) -> (-19.9, -23.55)
  line L108 (-29.9, -22.55) -> (-29.9, -23.55)
  line L109 (-19.9, -22.55) -> (-29.9, -22.55)
  line L110 (-19.9, -23.55) -> (-19.9, -22.55)
  line L111 (-29.9, -22.55) -> (-19.9, -23.55)
  line L112 (-19.9, -22.55) -> (-29.9, -23.55)
  line L113 (-69.9, 16.45) -> (-59.9, 16.45)
  line L114 (-69.9, 17.45) -> (-69.9, 16.45)
  line L115 (-59.9, 17.45) -> (-69.9, 17.45)
  line L116 (-59.9, 16.45) -> (-59.9, 17.45)
  line L117 (-69.9, 17.45) -> (-59.9, 16.45)
  line L118 (-59.9, 17.45) -> (-69.9, 16.45)
  line L119 (34.45, -29.05) -> (44.45, -29.05)
  line L120 (34.45, -44.05) -> (34.45, -29.05)
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  point P14 (64.9, -29.05)
  point P19 (64.9, -29.05)
  point P24 (-64.9, -29.05)
  point P29 (-64.9, -29.05)
  point P48 (0, 5.1849)
  point P49 (0, 5.1849)
  point P56 (25, -23.05)
  point P61 (64.9779, 16.9499)
  point P78 (-38.35, 44.85)
  point P79 (-38.35, 44.85)
  point P80 (-38.35, 32.25)
  point P85 (-38.35, 32.25)
  point P86 (-38.35, 57.45)
  point P91 (-38.35, 57.45)
  point P92 (38.35, 44.5695)
  point P103 (38.35, 44.5695)
  point P99 (38.35, 31.9695)
  point P102 (38.35, 31.9695)
  point P107 (38.35, 57.1695)
  point P108 (38.35, 57.1695)
  point P27 (-81.9, -46.05)
  point P42 (-81.9, -46.05)
  point P28 (-47.9, -46.05)
  point P43 (-47.9, -46.05)
  point P25 (-47.9, -12.05)
  point P41 (-47.9, -12.05)
  point P26 (-81.9, -12.05)
  point P40 (-81.9, -12.05)
  point P16 (47.9, -46.05)
  point P35 (47.9, -46.05)
  point P15 (81.9, -46.05)
  point P36 (81.9, -46.05)
  point P18 (81.9, -12.05)
  point P30 (81.9, -12.05)
  point P17 (47.9, -12.05)
  point P34 (47.9, -12.05)
  point P116 (-24.9, -23.05)
  point P121 (-64.9, 16.95)
  point P122 (44.45, -29.05)
  point P129 (64.9, -8.6)
  point P136 (-44.45, -29.05)
  point P143 (-64.9, -8.6)
  point P12 (44.45, -49.5)
  point P13 (85.35, -49.5)
  point P11 (44.45, -8.6)
  point P22 (-85.35, -49.5)
  point P23 (-44.45, -49.5)
  point P21 (-85.35, -8.6)
  point P45 (-4.35, 11.9349)
  point P46 (-4.35, -1.5651)
  point P47 (4.35, -1.5651)
  point P51 (24.9, -29.05)
  point P50 (64.9768, 10.9499)
  point P54 (30, -23.55)
  point P55 (20, -23.55)
  point P53 (30, -22.55)
  point P59 (69.9779, 17.4499)
  point P60 (59.9779, 17.4499)
  point P58 (69.9779, 16.4499)
  point P63 (19.25, 29.4)
  point P64 (19.25, 61.7)
  point P65 (-19.25, 61.7)
  point P68 (26.15, 62.2)
  point P69 (-20.25, 62.2)
  point P67 (26.15, 27.9)
  point P72 (30.85, 62.7)
  point P73 (-25.55, 62.7)
  point P71 (30.85, 27.3)
  point P76 (-35, 48.2)
  point P77 (-41.7, 48.2)
  point P75 (-35, 41.5)
  point P83 (-35, 35.6)
  point P84 (-41.7, 35.6)
  point P82 (-35, 28.9)
  point P89 (-35, 60.8)
  point P90 (-41.7, 60.8)
  point P88 (-35, 54.1)
  point P95 (41.7, 47.9195)
  point P96 (35, 47.9195)
  point P94 (41.7, 41.2195)
  point P98 (41.7, 35.3195)
  point P100 (35, 35.3195)
  point P97 (41.7, 28.6195)
  point P106 (41.7, 60.5195)
  point P109 (35, 60.5195)
  point P104 (41.7, 53.8195)
  point P110 (-24.9, -29.05)
  point P111 (-64.9, 10.95)
  point P114 (-29.9, -22.55)
  point P115 (-19.9, -22.55)
  point P113 (-29.9, -23.55)
  point P119 (-69.9, 17.45)
  point P120 (-59.9, 17.45)
  point P118 (-69.9, 16.45)
  point P123 (34.45, -29.05)
  point P125 (44.45, -44.05)
  point P126 (34.45, -29.05)
  point P128 (44.45, -19.05)
  point P130 (79.9, -8.6)
  point P132 (64.9, 1.4)
  point P133 (54.9, -8.6)
  point P135 (64.9, 1.4)
  point P137 (-34.45, -29.05)
  point P139 (-44.45, -44.05)
  point P140 (-34.45, -29.05)
  point P142 (-44.45, -19.05)
  point P144 (-54.9, -8.6)
  point P146 (-64.9, 1.4)
  point P147 (-79.9, -8.6)
  point P149 (-64.9, 1.4)
  perpendicular L9 L10
  parallel L9 L11
  parallel L10 L12
  horizontal L9
  coincident L13 P14
  coincident L14 P14
  perpendicular L15 L16
  parallel L15 L17
  parallel L16 L18
  horizontal L15
  coincident L19 P19
  coincident L20 P19
  coincident P14 P19
  perpendicular L21 L22
  parallel L21 L23
  parallel L22 L24
  horizontal L21
  coincident L25 P24
  coincident L26 P24
  perpendicular L27 L28
  parallel L27 L29
  parallel L28 L30
  horizontal L27
  coincident L31 P29
  coincident L32 P29
  coincident P24 P29
  perpendicular L35 L36
  parallel L35 L37
  parallel L36 L38
  horizontal L35
  coincident L39 P48
  coincident L40 P48
  coincident P48 P49
  perpendicular L41 L42
  parallel L41 L43
  parallel L42 L44
  horizontal L41
  coincident L45 P56
  coincident L46 P56
  perpendicular L47 L48
  parallel L47 L49
  parallel L48 L50
  horizontal L47
  coincident L51 P61
  coincident L52 P61
  perpendicular L53 L54
  parallel L53 L55
  parallel L54 L56
  horizontal L53
  perpendicular L59 L60
  parallel L59 L61
  parallel L60 L62
  horizontal L59
  perpendicular L65 L66
  parallel L65 L67
  parallel L66 L68
  horizontal L65
  perpendicular L71 L72
  parallel L71 L73
  parallel L72 L74
  horizontal L71
  coincident L75 P78
  coincident L76 P78
  coincident P78 P79
  perpendicular L77 L81
  parallel L80 L81
  parallel L77 L82
  horizontal L81
  coincident P80 L79
  coincident P80 L78
  coincident P80 P85
  perpendicular L84 L87
  parallel L87 L88
  parallel L84 L86
  horizontal L87
  coincident P86 L85
  coincident P86 L83
  coincident P86 P91
  perpendicular L95 L106
  parallel L103 L106
  parallel L92 L95
  horizontal L106
  coincident P92 L89
  coincident P92 L93
  coincident P92 P103
  perpendicular L98 L99
  parallel L90 L98
  parallel L94 L99
  horizontal L98
  coincident P99 L102
  coincident P99 L96
  coincident P99 P102
  perpendicular L97 L104
  parallel L104 L105
  parallel L97 L100
  horizontal L104
  coincident P107 L91
  coincident P107 L101
  coincident P107 P108
  coincident P27 P42
  coincident P28 P43
  coincident P25 P41
  coincident P26 P40
  coincident P16 P35
  coincident P15 P36
  coincident P18 P30
  coincident P17 P34
  horizontal L107
  perpendicular L107 L108
  parallel L107 L109
  parallel L108 L110
  coincident L111 P116
  coincident L112 P116
  horizontal L113
  perpendicular L113 L114
  parallel L113 L115
  parallel L114 L116
  coincident L117 P121
  coincident L118 P121
  horizontal L119
  vertical L120
  midpoint L10 P122
  midpoint L9 P129
  midpoint L24 P136
  midpoint L21 P143
  dimension "d201" distance P12 P13 = 40.9
  dimension "d202" distance P11 P12 = 40.9
  dimension "d203" distance P17 P18 = 34
  dimension "d204" distance P16 P17 = 34
  dimension "d205" distance P22 P23 = 40.9
  dimension "d206" distance P21 P22 = 40.9
  dimension "d207" distance P27 P28 = 34
  dimension "d208" distance P26 P27 = 34
  dimension "d209" diameter = 3
  dimension "d213" diameter = 3
  dimension "d214" diameter = 3
  dimension "d215" diameter = 3
  dimension "d223" diameter = 3
  dimension "d224" diameter = 3
  dimension "d225" diameter = 3
  dimension "d226" diameter = 3
  dimension "d243" distance P45 P46 = 13.5
  dimension "d244" distance P46 P47 = 8.7
  dimension "d245" diameter = 5.85
  dimension "d250" diameter = 7.1 (= "d251")
  dimension "d251" diameter = 7.1
  dimension "d252" distance P19 P51 = 40
  dimension "d253" distance P19 P50 = 40
  dimension "d254" distance P16 P51 = 17
  dimension "d255" distance P54 P55 = 10
  dimension "d256" distance P53 P54 = 1
  dimension "d257" distance P51 P56 = 6
  dimension "d258" distance P59 P60 = 10
  dimension "d259" distance P58 P59 = 1
  dimension "d260" distance P50 P61 = 6
  dimension "d269" distance P63 P64 = 32.3
  dimension "d270" distance P64 P65 = 38.5
  dimension "d271" distance P68 P69 = 46.4
  dimension "d272" distance P67 P68 = 34.3
  dimension "d273" distance P72 P73 = 56.4
  dimension "d274" distance P71 P72 = 35.4
  dimension "d283" distance P76 P77 = 6.7 (= "d307")
  dimension "d284" distance P75 P76 = 6.7 (= "d308")
  dimension "d285" diameter = 5 (= "d309")
  dimension "d286" distance P83 P84 = 6.7 (= "d307")
  dimension "d287" distance P82 P83 = 6.7 (= "d308")
  dimension "d288" diameter = 5 (= "d309")
  dimension "d289" distance P89 P90 = 6.7 (= "d307")
  dimension "d290" distance P88 P89 = 6.7 (= "d308")
  dimension "d291" diameter = 5 (= "d309")
  dimension "d295" distance L53 L81 = 0.5
  dimension "d300" distance P79 P80 = 12.6 (= "d313")
  dimension "d301" distance P79 P86 = 12.6 (= "d313")
  dimension "d303" = 0.5
  dimension "d304" distance P95 P96 = 6.7 (= "d307")
  dimension "d305" distance P94 P95 = 6.7 (= "d308")
  dimension "d306" diameter = 5 (= "d309")
  dimension "d307" distance P98 P100 = 6.7
  dimension "d308" distance P97 P98 = 6.7
  dimension "d309" diameter = 5
  dimension "d310" distance P106 P109 = 6.7 (= "d307")
  dimension "d311" distance P104 P106 = 6.7 (= "d308")
  dimension "d312" diameter = 5 (= "d309")
  dimension "d313" distance P99 P103 = 12.6
  dimension "d314" distance P103 P107 = 12.6 (= "d313")
  dimension "d365" distance L2 L22 = 9.65
  dimension "d366" distance L4 L23 = 30.5
  dimension "d367" distance L4 L11 = 30.5
  dimension "d368" distance L6 L12 = 9.65
  dimension "d369" diameter = 7.1 (= "d251")
  dimension "d370" distance P29 P110 = 40
  dimension "d371" distance P43 P110 = 17
  dimension "d372" diameter = 7.1 (= "d251")
  dimension "d373" distance P29 P111 = 40
  dimension "d374" distance P40 P111 = 17
  dimension "d375" distance P114 P115 = 10
  dimension "d376" distance P113 P114 = 1
  dimension "d377" distance P110 P116 = 6
  dimension "d378" distance P119 P120 = 10
  dimension "d379" distance P118 P119 = 1
  dimension "d380" distance P111 P121 = 6
  dimension "d382" distance L62 L68 = 5.3
  dimension "d384" distance L8 L67 = 17.3
  dimension "d385" distance L56 L62 = 1
  dimension "d386" distance L54 L60 = 6.9
  dimension "d387" distance L60 L66 = 4.7
  dimension "d388" distance L61 L67 = 0.5
  dimension "d389" distance L55 L61 = 0.5
  dimension "d390" distance L59 L65 = 0.6
  dimension "d391" distance L53 L59 = 1.5
  dimension "d405" distance P49 L77 = 35
  dimension "d406" distance P48 L72 = 35 (= "d405")
  dimension "d407" distance P48 L84 = 35 (= "d405")
  dimension "d410" distance P48 L100 = 35 (= "d405")
  dimension "d411" distance P49 L92 = 35 (= "d405")
  dimension "d412" distance L2 P49 = 95
  dimension "d413" distance P49 L94 = 35 (= "d405")
  dimension "d414" distance L2 L56 = 75.75 (= "d412 - d270 / 2")
  dimension "d417" distance P122 P123 = 10
  dimension "d418" distance P122 P125 = 15
  dimension "d419" distance P122 P126 = 10
  dimension "d420" distance P122 P128 = 10
  dimension "d421" distance P129 P130 = 15
  dimension "d422" distance P129 P132 = 10
  dimension "d423" distance P129 P133 = 10
  dimension "d424" distance P129 P135 = 10
  dimension "d425" distance P136 P137 = 10
  dimension "d426" distance P136 P139 = 15
  dimension "d427" distance P136 P140 = 10
  dimension "d428" distance P136 P142 = 10
  dimension "d429" distance P143 P144 = 10
  dimension "d430" distance P143 P146 = 10
  dimension "d431" distance P143 P147 = 15
  dimension "d432" distance P143 P149 = 10
  dimension "d433" distance = 0.4
  dimension "d434" distance = 5
  dimension "d435" distance = 5
  dimension "d436" distance = 1
extrude "Extrusion51" cut sketch "Skizze16" against normal blind 4
extrude "Extrusion52" cut of existing geometry blind -5
extrude "Extrusion80" cut sketch "Skizze16" against normal blind 11.9
extrude "Extrusion53" cut sketch "Skizze16" against normal blind 4
extrude "Extrusion54" cut sketch "Skizze16" against normal blind 5
extrude "Extrusion55" cut sketch "Skizze16" against normal blind 0.5
extrude "Extrusion56" cut sketch "Skizze16" against normal blind 5
extrude "Extrusion57" cut sketch "Skizze16" against normal blind 5
extrude "Extrusion58" cut sketch "Skizze16" profile of L41 L42 L43 L44 against normal blind 1
extrude "Extrusion59" cut sketch "Skizze16" against normal blind 5
extrude "Extrusion60" cut sketch "Skizze16" profile of L47 L48 L49 L50 against normal blind 1
extrude "Extrusion61" cut sketch "Skizze16" profile of L53 L54 L55 L56 against normal blind 5
extrude "Extrusion62" cut sketch "Skizze16" profile of L59 L60 L61 L62 L65 L66 L67 L68 against normal blind 1.3
extrude "Extrusion63" cut sketch "Skizze16" profile of L53 L54 L55 L56 L59 L60 L61 L62 against normal blind 3.8
extrude "Extrusion64" cut of existing geometry blind -4.5
extrude "Extrusion65" cut sketch "Skizze16" against normal blind 5
extrude "Extrusion66" cut sketch "Skizze16" against normal blind 4
extrude "Extrusion81" cut sketch "Skizze16" against normal blind 38
extrude "Extrusion82" cut sketch "Skizze16" profile of L113 L114 L115 L116 against normal blind 1
extrude "Extrusion83" cut sketch "Skizze16" profile of L107 L108 L109 L110 against normal blind 1
extrude "Extrusion84" cut sketch "Skizze16" against normal blind 10
fillet "Abrundung27" radius 1
fillet "Abrundung28" radius 1
extrude "Extrusion67" cut of existing geometry blind -0.3
extrude "Extrusion68" cut of existing geometry blind -0.3
extrude "Extrusion69" cut of existing geometry blind -0.3
extrude "Extrusion70" cut of existing geometry blind -0.3
extrude "Extrusion71" cut of existing geometry blind -0.3
extrude "Extrusion72" cut of existing geometry blind -0.3
extrude "Extrusion73" cut of existing geometry blind -0.3
extrude "Extrusion74" cut of existing geometry blind -0.3
extrude "Extrusion75" cut of existing geometry blind -0.3
extrude "Extrusion76" cut of existing geometry blind -0.2
sketch "Skizze21" plane through (0, 0, 15) normal (0, 0, 1) x axis (-1, 0, 0)
  line L1 (6.7499, 85) -> (6.7499, 80)
  line L2 (0.7499, 85) -> (6.7499, 85)
  line L3 (0.7499, 80) -> (0.7499, 85)
  line L4 (6.7499, 80) -> (0.7499, 80)
  line L5 (0.7499, 82.5) -> (6.7499, 82.5)
  point P6 (6.7499, 82.5)
  point P7 (0.7499, 82.5)
  midpoint L1 P6
  midpoint L3 P7
extrude "Extrusion78" add sketch "Skizze21" profile of L1 L2 L3 L5 along normal blind 4.95
sketch "Skizze22" plane through (0, 0, 15) normal (0, 0, 1) x axis (-1, 0, 0)
  line L1 (-8.5001, 80) -> (-12.0001, 80)
  line L2 (-8.5001, 85) -> (-8.5001, 80)
  line L3 (-12.0001, 85) -> (-8.5001, 85)
  line L4 (-12.0001, 80) -> (-12.0001, 85)
  line L5 (-12.0001, 82.5) -> (-8.5001, 82.5)
  point P6 (-8.5001, 82.5)
  point P7 (-12.0001, 82.5)
  midpoint L2 P6
  midpoint L4 P7
extrude "Extrusion79" add sketch "Skizze22" profile of L2 L3 L4 L5 along normal blind 4.99
move "Verschieben4"
move "Verschieben5"
component_from_bodies "Körper->Berechn1"
component_from_bodies "Körper->Berechn2"
extrude "Extrusion1" cut of existing geometry blind -0.1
